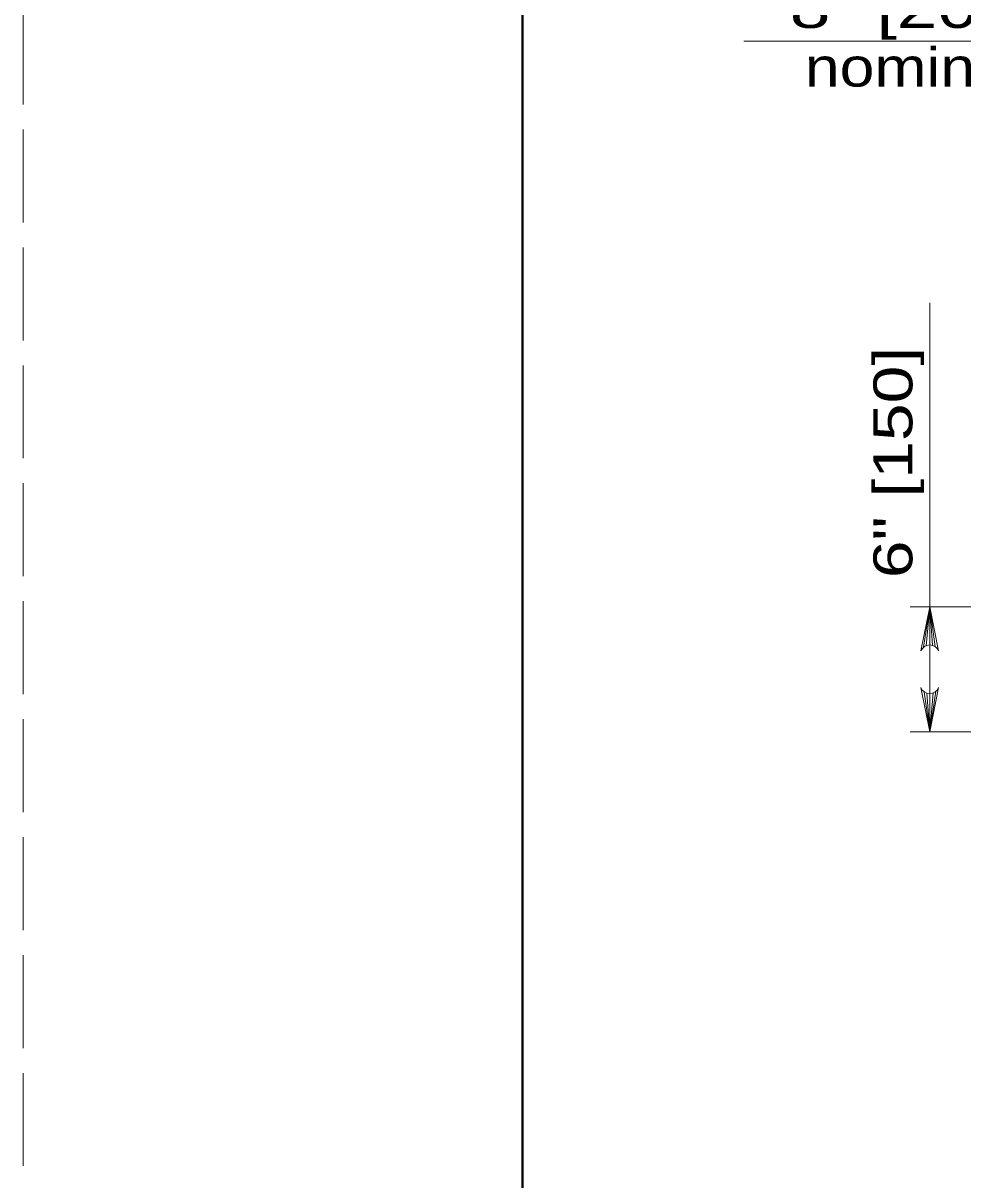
# Model space of a CAD drawing. Extents: x 1083.1 to 1117.1, y 697.4 to 741.4.
# Drawn here: x 1083.126 to 1086.89, y 727.71 to 732.34 of the extents above; entities that cross this region are included whole.
import ezdxf
from ezdxf.enums import TextEntityAlignment as Align

# ---------------------------------------------------------------- set-up
doc = ezdxf.new("R2010")
doc.units = 0
doc.header["$LTSCALE"] = 0.062
doc.linetypes.add('LONG_DASHED', pattern=[7.5, 6, -1.5])
doc.layers.add('1', color=7, linetype='Continuous', lineweight=13)

msp = doc.modelspace()

# ---------------------------------------------------------------- linework, layer by layer
at = {"layer": '1'}
for p, q in [((1087.75233, 732.26683), (1086.01308, 732.26683)), ((1086.75717, 729.50342), (1086.75717, 731.22042)), ((1086.6785, 730.00417), (1087.68192, 730.00417)), ((1086.73242, 729.842), (1086.75717, 730.00417)), ((1086.74275, 729.84817), (1086.75717, 730.00417)), ((1086.75717, 729.851), (1086.75717, 730.00417)), ((1086.7685, 729.84933), (1086.75717, 730.00417)), ((1086.77958, 729.84392), (1086.75717, 730.00417)), ((1086.73475, 729.66367), (1086.75717, 729.50342)), ((1086.74583, 729.65825), (1086.75717, 729.50342)), ((1086.78192, 729.66558), (1086.75717, 729.50342)), ((1086.77158, 729.65942), (1086.75717, 729.50342)), ((1086.75717, 729.65658), (1086.75717, 729.50342)), ((1086.6785, 729.50342), (1087.67117, 729.50342))]:
    msp.add_line(p, q, dxfattribs=at)
at = {"layer": '1', "linetype": 'LONG_DASHED'}
msp.add_lwpolyline([(1083.12642, 719.35408), (1117.12642, 719.35408), (1117.12642, 741.35408), (1083.12642, 741.35408)], close=True, dxfattribs=at)
at = {"layer": '1', "lineweight": 25}
msp.add_lwpolyline([(1116.62642, 719.85408), (1085.12642, 719.85408), (1085.12642, 740.85408)], dxfattribs=at)
at = {"layer": '1', "lineweight": 40}
msp.add_lwpolyline([(1085.12642, 740.85408), (1116.62642, 740.85408), (1116.62642, 719.85408), (1085.12642, 719.85408)], close=True, dxfattribs=at)
at = {"layer": '1'}
for points in [[(1086.72175, 729.82717), (1086.75717, 730.00417), (1086.79258, 729.82717)], [(1086.79258, 729.68042), (1086.75717, 729.50342), (1086.72175, 729.68042)]]:
    msp.add_lwpolyline(points, dxfattribs=at)
for centre, start, end in [((1086.7572, 729.81288), 22.08782, 157.91395), ((1086.75712, 729.69475), 202.08782, 337.91395)]:
    msp.add_arc(centre, 0.0382, start, end, dxfattribs=at)

# ---------------------------------------------------------------- texts
for s, width, p in [('8" [200]', 1.4, (1086.69538, 732.32025)), ('nominal', 1.2, (1086.69542, 732.08558))]:
    msp.add_text(s, height=0.156, dxfattribs=dict(at, width=width)).set_placement(p, align=Align.CENTER)
at = {"layer": '1', "width": 1.3}
msp.add_text('6" [150]', height=0.156, rotation=90, dxfattribs=at).set_placement((1086.68767, 730.11842))

doc.saveas('drawing.dxf')
